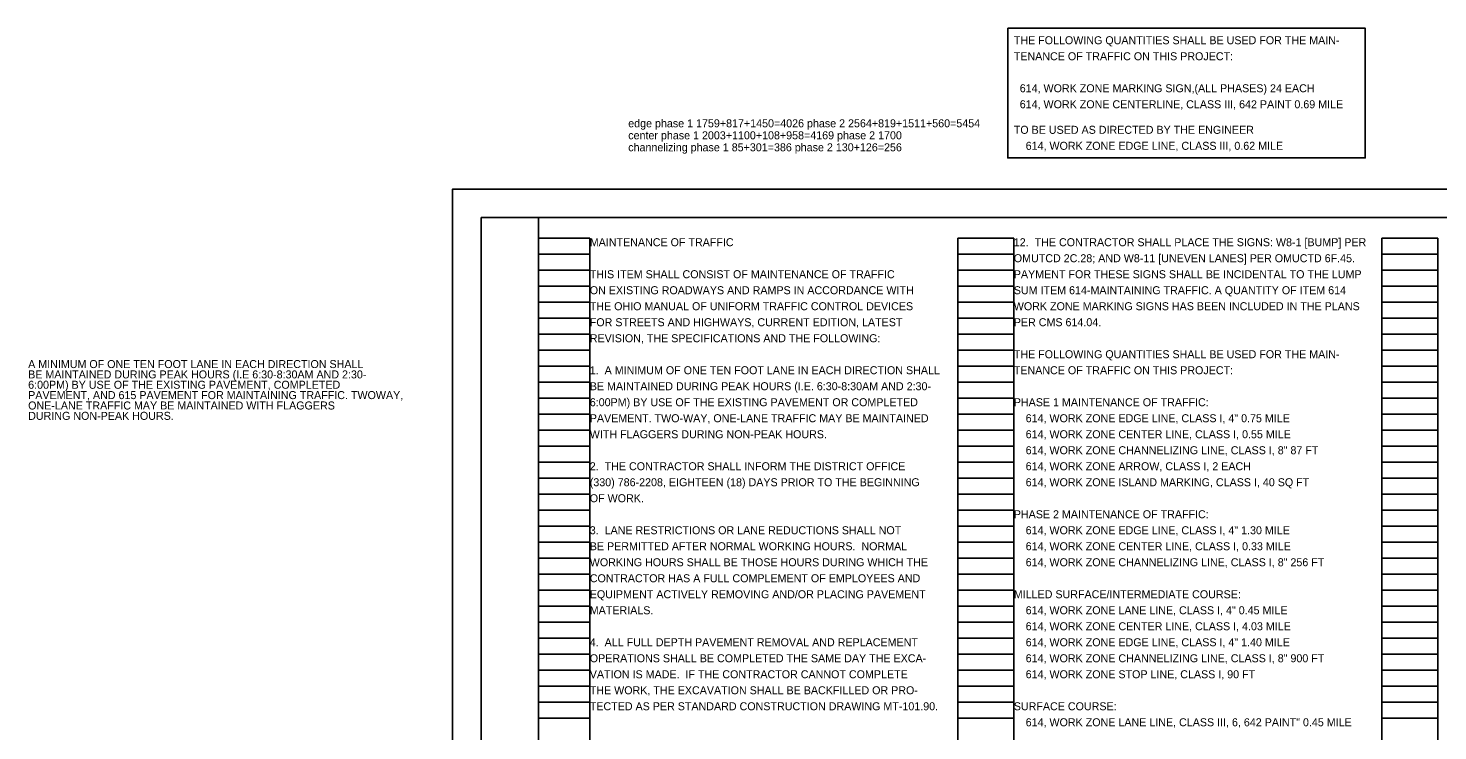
# Model space of a CAD drawing. Extents: x -7.4 to 41.7, y -6.6 to 28.2.
# Drawn here: x -7.43 to 17.24, y 12.52 to 24.82 of the extents above; entities that cross this region are included whole.
import ezdxf

# ---------------------------------------------------------------- set-up
doc = ezdxf.new("R2010")
doc.units = 0
for name, color, linetype in [('Default', 7, 'Continuous'), ('SH_Border', 7, 'Continuous'), ('SH_Cut_Line', 7, 'Continuous'), ('SH_Data', 7, 'Continuous'), ('SH_Text', 7, 'Continuous')]:
    doc.layers.add(name, color=color, linetype=linetype)

msp = doc.modelspace()

# ---------------------------------------------------------------- linework, layer by layer
at = {"layer": 'Default'}
msp.add_lwpolyline([(9.715, 24.815), (15.97, 24.815), (15.97, 22.545), (9.715, 22.545)], close=True, dxfattribs=at)
at = {"layer": 'SH_Border'}
for points in [[(0.5, 21.5), (1.5, 21.5), (1.5, 0.5), (0.5, 0.5)], [(1.5, 21.5), (33.5, 21.5), (33.5, 0.5), (1.5, 0.5)]]:
    msp.add_lwpolyline(points, close=True, dxfattribs=at)
at = {"layer": 'SH_Cut_Line'}
msp.add_lwpolyline([(0, 0), (34, 0), (34, 22), (0, 22)], close=True, dxfattribs=at)
at = {"layer": 'SH_Data'}
for p, q in [((1.5, 0.98), (1.5, 21.14)), ((1.5, 21.14), (2.4, 21.14)), ((2.4, 0.98), (2.4, 21.14)), ((8.84, 0.98), (8.84, 21.14)), ((8.84, 21.14), (9.82, 21.14)), ((9.82, 0.98), (9.82, 21.14)), ((16.26, 0.98), (16.26, 21.14)), ((16.26, 21.14), (17.24, 21.14)), ((17.24, 0.98), (17.24, 21.14)), ((1.5, 20.86), (2.4, 20.86)), ((8.84, 20.86), (9.82, 20.86)), ((16.26, 20.86), (17.24, 20.86)), ((1.5, 20.58), (2.4, 20.58)), ((8.84, 20.58), (9.82, 20.58)), ((16.26, 20.58), (17.24, 20.58)), ((1.5, 20.3), (2.4, 20.3)), ((8.84, 20.3), (9.82, 20.3)), ((16.26, 20.3), (17.24, 20.3)), ((1.5, 20.02), (2.4, 20.02)), ((8.84, 20.02), (9.82, 20.02)), ((16.26, 20.02), (17.24, 20.02)), ((1.5, 19.74), (2.4, 19.74)), ((8.84, 19.74), (9.82, 19.74)), ((16.26, 19.74), (17.24, 19.74)), ((1.5, 19.46), (2.4, 19.46)), ((8.84, 19.46), (9.82, 19.46)), ((16.26, 19.46), (17.24, 19.46)), ((1.5, 19.18), (2.4, 19.18)), ((8.84, 19.18), (9.82, 19.18)), ((16.26, 19.18), (17.24, 19.18)), ((1.5, 18.9), (2.4, 18.9)), ((8.84, 18.9), (9.82, 18.9)), ((16.26, 18.9), (17.24, 18.9)), ((1.5, 18.62), (2.4, 18.62)), ((8.84, 18.62), (9.82, 18.62)), ((16.26, 18.62), (17.24, 18.62)), ((1.5, 18.34), (2.4, 18.34)), ((8.84, 18.34), (9.82, 18.34)), ((16.26, 18.34), (17.24, 18.34)), ((1.5, 18.06), (2.4, 18.06)), ((8.84, 18.06), (9.82, 18.06)), ((16.26, 18.06), (17.24, 18.06)), ((1.5, 17.78), (2.4, 17.78)), ((8.84, 17.78), (9.82, 17.78)), ((16.26, 17.78), (17.24, 17.78)), ((1.5, 17.5), (2.4, 17.5)), ((8.84, 17.5), (9.82, 17.5)), ((16.26, 17.5), (17.24, 17.5)), ((1.5, 17.22), (2.4, 17.22)), ((8.84, 17.22), (9.82, 17.22)), ((16.26, 17.22), (17.24, 17.22)), ((1.5, 16.94), (2.4, 16.94)), ((8.84, 16.94), (9.82, 16.94)), ((16.26, 16.94), (17.24, 16.94)), ((1.5, 16.66), (2.4, 16.66)), ((8.84, 16.66), (9.82, 16.66)), ((16.26, 16.66), (17.24, 16.66)), ((1.5, 16.38), (2.4, 16.38)), ((8.84, 16.38), (9.82, 16.38)), ((16.26, 16.38), (17.24, 16.38)), ((1.5, 16.1), (2.4, 16.1)), ((8.84, 16.1), (9.82, 16.1)), ((16.26, 16.1), (17.24, 16.1)), ((1.5, 15.82), (2.4, 15.82)), ((8.84, 15.82), (9.82, 15.82)), ((16.26, 15.82), (17.24, 15.82)), ((1.5, 15.54), (2.4, 15.54)), ((8.84, 15.54), (9.82, 15.54)), ((16.26, 15.54), (17.24, 15.54)), ((1.5, 15.26), (2.4, 15.26)), ((8.84, 15.26), (9.82, 15.26)), ((16.26, 15.26), (17.24, 15.26)), ((1.5, 14.98), (2.4, 14.98)), ((8.84, 14.98), (9.82, 14.98)), ((16.26, 14.98), (17.24, 14.98)), ((1.5, 14.7), (2.4, 14.7)), ((8.84, 14.7), (9.82, 14.7)), ((16.26, 14.7), (17.24, 14.7)), ((1.5, 14.42), (2.4, 14.42)), ((8.84, 14.42), (9.82, 14.42)), ((16.26, 14.42), (17.24, 14.42)), ((1.5, 14.14), (2.4, 14.14)), ((8.84, 14.14), (9.82, 14.14)), ((16.26, 14.14), (17.24, 14.14)), ((1.5, 13.86), (2.4, 13.86)), ((8.84, 13.86), (9.82, 13.86)), ((16.26, 13.86), (17.24, 13.86)), ((1.5, 13.58), (2.4, 13.58)), ((8.84, 13.58), (9.82, 13.58)), ((16.26, 13.58), (17.24, 13.58)), ((1.5, 13.3), (2.4, 13.3)), ((8.84, 13.3), (9.82, 13.3)), ((16.26, 13.3), (17.24, 13.3)), ((1.5, 13.02), (2.4, 13.02)), ((8.84, 13.02), (9.82, 13.02)), ((16.26, 13.02), (17.24, 13.02)), ((1.5, 12.74), (2.4, 12.74)), ((8.84, 12.74), (9.82, 12.74)), ((16.26, 12.74), (17.24, 12.74))]:
    msp.add_line(p, q, dxfattribs=at)

# ---------------------------------------------------------------- texts
at = {"layer": 'SH_Text'}
for s, p in [('THE FOLLOWING QUANTITIES SHALL BE USED FOR THE MAIN-', (9.82, 24.534)), ('TENANCE OF TRAFFIC ON THIS PROJECT:', (9.82, 24.254)), ('  614, WORK ZONE MARKING SIGN,(ALL PHASES) 24 EACH', (9.82, 23.694)), ('  614, WORK ZONE CENTERLINE, CLASS III, 642 PAINT 0.69 MILE', (9.82, 23.414)), ('edge phase 1 1759+817+1450=4026 phase 2 2564+819+1511+560=5454', (3.073, 23.081)), ('center phase 1 2003+1100+108+958=4169 phase 2 1700', (3.073, 22.871)), ('TO BE USED AS DIRECTED BY THE ENGINEER', (9.82, 22.967)), ('channelizing phase 1 85+301=386 phase 2 130+126=256', (3.073, 22.661)), ('    614, WORK ZONE EDGE LINE, CLASS III, 0.62 MILE', (9.82, 22.687)), ('MAINTENANCE OF TRAFFIC', (2.4, 21)), ('12.  THE CONTRACTOR SHALL PLACE THE SIGNS: W8-1 [BUMP] PER', (9.82, 21)), ('OMUTCD 2C.28; AND W8-11 [UNEVEN LANES] PER OMUCTD 6F.45.', (9.82, 20.72)), ('THIS ITEM SHALL CONSIST OF MAINTENANCE OF TRAFFIC', (2.4, 20.44)), ('PAYMENT FOR THESE SIGNS SHALL BE INCIDENTAL TO THE LUMP ', (9.82, 20.44)), ('ON EXISTING ROADWAYS AND RAMPS IN ACCORDANCE WITH', (2.4, 20.16)), ('SUM ITEM 614-MAINTAINING TRAFFIC. A QUANTITY OF ITEM 614 ', (9.82, 20.16)), ('THE OHIO MANUAL OF UNIFORM TRAFFIC CONTROL DEVICES', (2.4, 19.88)), ('WORK ZONE MARKING SIGNS HAS BEEN INCLUDED IN THE PLANS', (9.82, 19.88)), ('FOR STREETS AND HIGHWAYS, CURRENT EDITION, LATEST', (2.4, 19.6)), ('PER CMS 614.04.', (9.82, 19.6)), ('REVISION, THE SPECIFICATIONS AND THE FOLLOWING:', (2.4, 19.32)), ('A MINIMUM OF ONE TEN FOOT LANE IN EACH DIRECTION SHALL', (-7.428, 18.868)), ('THE FOLLOWING QUANTITIES SHALL BE USED FOR THE MAIN-', (9.82, 19.04)), ('BE MAINTAINED DURING PEAK HOURS (I.E 6:30-8:30AM AND 2:30-', (-7.428, 18.687)), ('1.  A MINIMUM OF ONE TEN FOOT LANE IN EACH DIRECTION SHALL', (2.4, 18.76)), ('TENANCE OF TRAFFIC ON THIS PROJECT:', (9.82, 18.76)), ('6:00PM) BY USE OF THE EXISTING PAVEMENT, COMPLETED', (-7.428, 18.506)), ('BE MAINTAINED DURING PEAK HOURS (I.E. 6:30-8:30AM AND 2:30-', (2.4, 18.48)), ('ONE-LANE TRAFFIC MAY BE MAINTAINED WITH FLAGGERS', (-7.428, 18.143)), ('PAVEMENT, AND 615 PAVEMENT FOR MAINTAINING TRAFFIC. TWOWAY,', (-7.428, 18.325)), ('6:00PM) BY USE OF THE EXISTING PAVEMENT OR COMPLETED', (2.4, 18.2)), ('PHASE 1 MAINTENANCE OF TRAFFIC:', (9.82, 18.2)), ('DURING NON-PEAK HOURS.', (-7.428, 17.962)), ('PAVEMENT. TWO-WAY, ONE-LANE TRAFFIC MAY BE MAINTAINED', (2.4, 17.92)), ('    614, WORK ZONE EDGE LINE, CLASS I, 4" 0.75 MILE', (9.82, 17.92)), ('WITH FLAGGERS DURING NON-PEAK HOURS. ', (2.4, 17.64)), ('    614, WORK ZONE CENTER LINE, CLASS I, 0.55 MILE', (9.82, 17.64)), ('    614, WORK ZONE CHANNELIZING LINE, CLASS I, 8" 87 FT', (9.82, 17.36)), ('2.  THE CONTRACTOR SHALL INFORM THE DISTRICT OFFICE', (2.4, 17.08)), ('    614, WORK ZONE ARROW, CLASS I, 2 EACH', (9.82, 17.08)), ('(330) 786-2208, EIGHTEEN (18) DAYS PRIOR TO THE BEGINNING', (2.4, 16.8)), ('    614, WORK ZONE ISLAND MARKING, CLASS I, 40 SQ FT', (9.82, 16.8)), ('OF WORK.', (2.4, 16.52)), ('PHASE 2 MAINTENANCE OF TRAFFIC:', (9.82, 16.24)), ('3.  LANE RESTRICTIONS OR LANE REDUCTIONS SHALL NOT', (2.4, 15.96)), ('    614, WORK ZONE EDGE LINE, CLASS I, 4" 1.30 MILE', (9.82, 15.96)), ('BE PERMITTED AFTER NORMAL WORKING HOURS.  NORMAL', (2.4, 15.68)), ('    614, WORK ZONE CENTER LINE, CLASS I, 0.33 MILE', (9.82, 15.68)), ('WORKING HOURS SHALL BE THOSE HOURS DURING WHICH THE', (2.4, 15.4)), ('    614, WORK ZONE CHANNELIZING LINE, CLASS I, 8" 256 FT', (9.82, 15.4)), ('CONTRACTOR HAS A FULL COMPLEMENT OF EMPLOYEES AND', (2.4, 15.12)), ('EQUIPMENT ACTIVELY REMOVING AND/OR PLACING PAVEMENT', (2.4, 14.84)), ('MILLED SURFACE/INTERMEDIATE COURSE:', (9.82, 14.84)), ('MATERIALS.', (2.4, 14.56)), ('    614, WORK ZONE LANE LINE, CLASS I, 4" 0.45 MILE', (9.82, 14.56)), ('    614, WORK ZONE CENTER LINE, CLASS I, 4.03 MILE', (9.82, 14.28)), ('4.  ALL FULL DEPTH PAVEMENT REMOVAL AND REPLACEMENT', (2.4, 14)), ('    614, WORK ZONE EDGE LINE, CLASS I, 4" 1.40 MILE', (9.82, 14)), ('OPERATIONS SHALL BE COMPLETED THE SAME DAY THE EXCA-', (2.4, 13.72)), ('    614, WORK ZONE CHANNELIZING LINE, CLASS I, 8" 900 FT', (9.82, 13.72)), ('VATION IS MADE.  IF THE CONTRACTOR CANNOT COMPLETE', (2.4, 13.44)), ('    614, WORK ZONE STOP LINE, CLASS I, 90 FT', (9.82, 13.44)), ('THE WORK, THE EXCAVATION SHALL BE BACKFILLED OR PRO-', (2.4, 13.16)), ('TECTED AS PER STANDARD CONSTRUCTION DRAWING MT-101.90.', (2.4, 12.88)), ('SURFACE COURSE:', (9.82, 12.88)), ('    614, WORK ZONE LANE LINE, CLASS III, 6, 642 PAINT" 0.45 MILE', (9.82, 12.6))]:
    msp.add_text(s, height=0.14, dxfattribs=at).set_placement(p)

doc.saveas('drawing.dxf')
